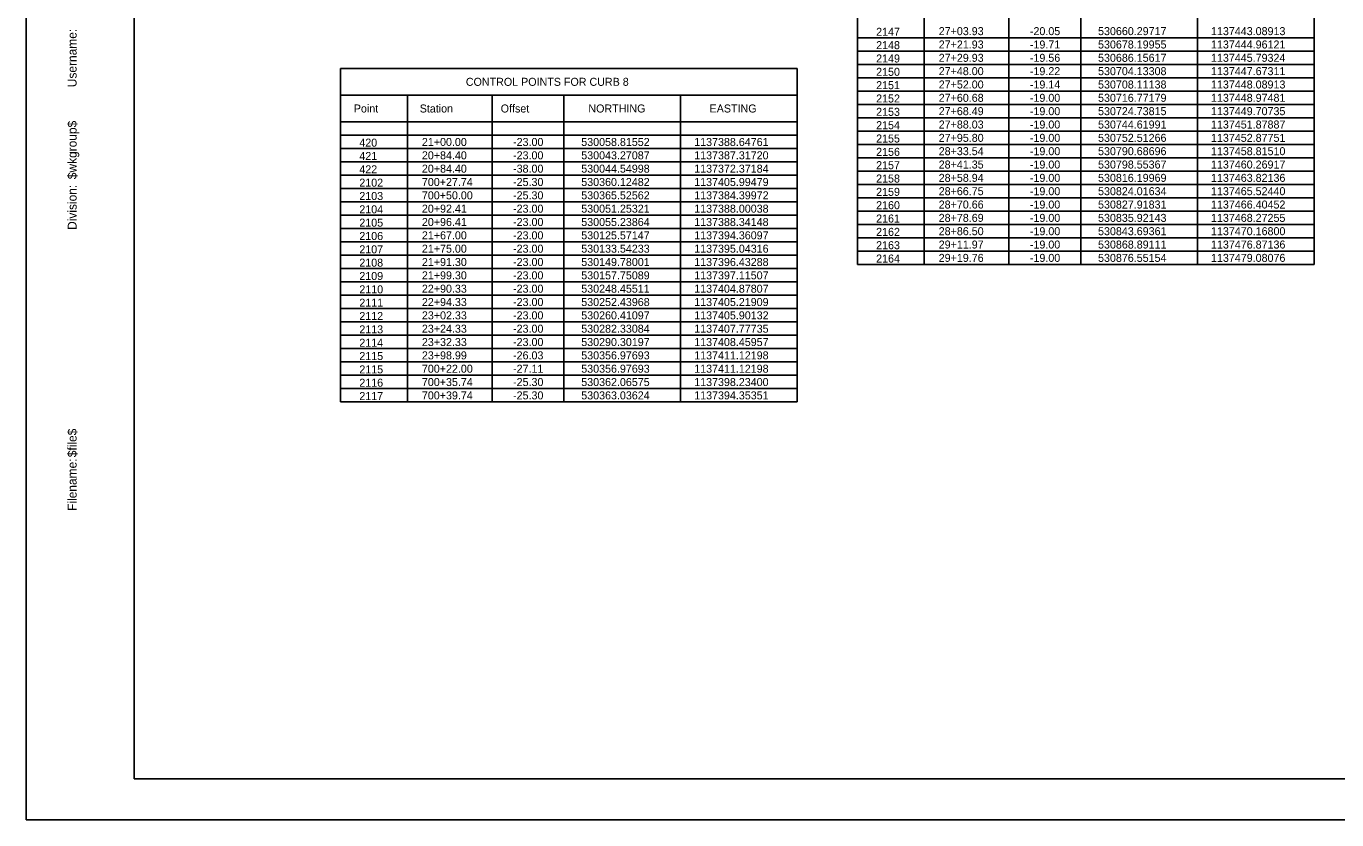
# Model space of a CAD drawing. Extents: x 0 to 850, y 0 to 550.
# Drawn here: x -0.1 to 491.2, y -0.1 to 297.4 of the extents above; entities that cross this region are included whole.
import ezdxf

# ---------------------------------------------------------------- set-up
doc = ezdxf.new("R2010")
doc.units = 0
for name, color, linetype in [('ANNOTATION', 7, 'Continuous'), ('BORDER', 7, 'Continuous'), ('Default', 7, 'Continuous'), ('H_V CONTROLS', 7, 'Continuous'), ('PLOT BOUNDARY', 7, 'Continuous')]:
    doc.layers.add(name, color=color, linetype=linetype)

msp = doc.modelspace()

# ---------------------------------------------------------------- linework, layer by layer
at = {"layer": 'BORDER'}
for p, q in [((40.33, 540.24), (40.33, 15.24)), ((40.33, 15.24), (840.33, 15.24))]:
    msp.add_line(p, q, dxfattribs=at)
at = {"layer": 'Default'}
msp.add_lwpolyline([(40.33, 15.24), (790.33, 15.24), (790.33, 540.26), (40.33, 540.26)], close=True, dxfattribs=at)
at = {"layer": 'H_V CONTROLS'}
for p, q in [((311.48, 483.15), (311.48, 208.15)), ((482.71, 483.15), (482.71, 208.15)), ((336.52, 473.15), (336.52, 208.15)), ((368.3, 473.15), (368.3, 208.15)), ((395.21, 473.15), (395.21, 208.15)), ((438.96, 473.15), (438.96, 208.15)), ((311.48, 293.15), (482.71, 293.15)), ((311.48, 288.15), (482.71, 288.15)), ((117.72, 281.6), (288.95, 281.6)), ((117.72, 281.6), (117.72, 156.6)), ((288.95, 281.6), (288.95, 156.6)), ((311.48, 283.15), (482.71, 283.15)), ((311.48, 278.15), (482.71, 278.15)), ((117.72, 271.6), (288.95, 271.6)), ((142.76, 271.6), (142.76, 156.6)), ((174.53, 271.6), (174.53, 156.6)), ((201.45, 271.6), (201.45, 156.6)), ((245.2, 271.6), (245.2, 156.6)), ((311.48, 273.15), (482.71, 273.15)), ((311.48, 268.15), (482.71, 268.15)), ((117.72, 261.6), (288.95, 261.6)), ((311.48, 263.15), (482.71, 263.15)), ((117.72, 256.6), (288.95, 256.6)), ((311.48, 258.15), (482.71, 258.15)), ((117.72, 251.6), (288.95, 251.6)), ((311.48, 253.15), (482.71, 253.15)), ((117.72, 246.6), (288.95, 246.6)), ((311.48, 248.15), (482.71, 248.15)), ((117.72, 241.6), (288.95, 241.6)), ((311.48, 243.15), (482.71, 243.15)), ((117.72, 236.6), (288.95, 236.6)), ((311.48, 238.15), (482.71, 238.15)), ((117.72, 231.6), (288.95, 231.6)), ((311.48, 233.15), (482.71, 233.15)), ((117.72, 226.6), (288.95, 226.6)), ((311.48, 228.15), (482.71, 228.15)), ((117.72, 221.6), (288.95, 221.6)), ((311.48, 223.15), (482.71, 223.15)), ((117.72, 216.6), (288.95, 216.6)), ((311.48, 218.15), (482.71, 218.15)), ((117.72, 211.6), (288.95, 211.6)), ((311.48, 213.15), (482.71, 213.15)), ((117.72, 206.6), (288.95, 206.6)), ((311.48, 208.15), (482.71, 208.15)), ((117.72, 201.6), (288.95, 201.6)), ((117.72, 196.6), (288.95, 196.6)), ((117.72, 191.6), (288.95, 191.6)), ((117.72, 186.6), (288.95, 186.6)), ((117.72, 181.6), (288.95, 181.6)), ((117.72, 176.6), (288.95, 176.6)), ((117.72, 171.6), (288.95, 171.6)), ((117.72, 166.6), (288.95, 166.6)), ((117.72, 161.6), (288.95, 161.6)), ((117.72, 156.6), (288.95, 156.6)), ((117.72, 156.6), (288.95, 156.6))]:
    msp.add_line(p, q, dxfattribs=at)
at = {"layer": 'PLOT BOUNDARY'}
msp.add_lwpolyline([(-0.13, -0.05), (849.87, -0.05), (849.87, 549.95), (-0.13, 549.95)], close=True, dxfattribs=at)

# ---------------------------------------------------------------- texts
at = {"layer": 'ANNOTATION'}
for s, p in [('2147', (318.51, 293.85)), ('27+03.93', (341.97, 294.1)), ('-20.05', (376.16, 294.1)), ('530660.29717', (401.71, 294.1)), ('1137443.08913', (444.06, 294.1)), ('2148', (318.51, 288.85)), ('27+21.93', (341.97, 289.1)), ('-19.71', (376.16, 289.1)), ('530678.19955', (401.71, 289.1)), ('1137444.96121', (444.06, 289.1)), ('2149', (318.51, 283.85)), ('27+29.93', (341.97, 284.1)), ('-19.56', (376.16, 284.1)), ('530686.15617', (401.71, 284.1)), ('1137445.79324', (444.06, 284.1)), ('2150', (318.51, 278.85)), ('27+48.00', (341.97, 279.1)), ('-19.22', (376.16, 279.1)), ('530704.13308', (401.71, 279.1)), ('1137447.67311', (444.06, 279.1)), ('2151', (318.51, 273.85)), ('27+52.00', (341.97, 274.1)), ('-19.14', (376.16, 274.1)), ('530708.11138', (401.71, 274.1)), ('1137448.08913', (444.06, 274.1)), ('2152', (318.51, 268.85)), ('27+60.68', (341.97, 269.1)), ('-19.00', (376.16, 269.1)), ('530716.77179', (401.71, 269.1)), ('1137448.97481', (444.06, 269.1)), ('2153', (318.51, 263.85)), ('27+68.49', (341.97, 264.1)), ('-19.00', (376.16, 264.1)), ('530724.73815', (401.71, 264.1)), ('1137449.70735', (444.06, 264.1)), ('2154', (318.51, 258.85)), ('27+88.03', (341.97, 259.1)), ('-19.00', (376.16, 259.1)), ('530744.61991', (401.71, 259.1)), ('1137451.87887', (444.06, 259.1)), ('21+00.00', (148.21, 252.55)), ('-23.00', (182.39, 252.55)), ('530058.81552', (207.95, 252.55)), ('1137388.64761', (250.3, 252.55)), ('2155', (318.51, 253.85)), ('27+95.80', (341.97, 254.1)), ('-19.00', (376.16, 254.1)), ('530752.51266', (401.71, 254.1)), ('1137452.87751', (444.06, 254.1)), ('420', (124.75, 252.3)), ('20+84.40', (148.21, 247.55)), ('-23.00', (182.39, 247.55)), ('530043.27087', (207.95, 247.55)), ('1137387.31720', (250.3, 247.55)), ('2156', (318.51, 248.85)), ('28+33.54', (341.97, 249.1)), ('-19.00', (376.16, 249.1)), ('530790.68696', (401.71, 249.1)), ('1137458.81510', (444.06, 249.1)), ('421', (124.75, 247.3)), ('2157', (318.51, 243.85)), ('28+41.35', (341.97, 244.1)), ('-19.00', (376.16, 244.1)), ('530798.55367', (401.71, 244.1)), ('1137460.26917', (444.06, 244.1)), ('422', (124.75, 242.3)), ('20+84.40', (148.21, 242.55)), ('-38.00', (182.39, 242.55)), ('530044.54998', (207.95, 242.55)), ('1137372.37184', (250.3, 242.55)), ('2158', (318.51, 238.85)), ('28+58.94', (341.97, 239.1)), ('-19.00', (376.16, 239.1)), ('530816.19969', (401.71, 239.1)), ('1137463.82136', (444.06, 239.1)), ('2102', (124.75, 237.3)), ('700+27.74', (148.21, 237.55)), ('-25.30', (182.39, 237.55)), ('530360.12482', (207.95, 237.55)), ('1137405.99479', (250.3, 237.55)), ('2159', (318.51, 233.85)), ('28+66.75', (341.97, 234.1)), ('-19.00', (376.16, 234.1)), ('530824.01634', (401.71, 234.1)), ('1137465.52440', (444.06, 234.1)), ('2103', (124.75, 232.3)), ('700+50.00', (148.21, 232.55)), ('-25.30', (182.39, 232.55)), ('530365.52562', (207.95, 232.55)), ('1137384.39972', (250.3, 232.55)), ('2160', (318.51, 228.85)), ('28+70.66', (341.97, 229.1)), ('-19.00', (376.16, 229.1)), ('530827.91831', (401.71, 229.1)), ('1137466.40452', (444.06, 229.1)), ('2104', (124.75, 227.3)), ('20+92.41', (148.21, 227.55)), ('-23.00', (182.39, 227.55)), ('530051.25321', (207.95, 227.55)), ('1137388.00038', (250.3, 227.55)), ('2161', (318.51, 223.85)), ('28+78.69', (341.97, 224.1)), ('-19.00', (376.16, 224.1)), ('530835.92143', (401.71, 224.1)), ('1137468.27255', (444.06, 224.1)), ('2105', (124.75, 222.3)), ('20+96.41', (148.21, 222.55)), ('-23.00', (182.39, 222.55)), ('530055.23864', (207.95, 222.55)), ('1137388.34148', (250.3, 222.55)), ('2162', (318.51, 218.85)), ('28+86.50', (341.97, 219.1)), ('-19.00', (376.16, 219.1)), ('530843.69361', (401.71, 219.1)), ('1137470.16800', (444.06, 219.1)), ('2106', (124.75, 217.3)), ('21+67.00', (148.21, 217.55)), ('-23.00', (182.39, 217.55)), ('530125.57147', (207.95, 217.55)), ('1137394.36097', (250.3, 217.55)), ('2163', (318.51, 213.85)), ('29+11.97', (341.97, 214.1)), ('-19.00', (376.16, 214.1)), ('530868.89111', (401.71, 214.1)), ('1137476.87136', (444.06, 214.1)), ('2107', (124.75, 212.3)), ('21+75.00', (148.21, 212.55)), ('-23.00', (182.39, 212.55)), ('530133.54233', (207.95, 212.55)), ('1137395.04316', (250.3, 212.55)), ('2164', (318.51, 208.85)), ('29+19.76', (341.97, 209.1)), ('-19.00', (376.16, 209.1)), ('530876.55154', (401.71, 209.1)), ('1137479.08076', (444.06, 209.1)), ('2108', (124.75, 207.3)), ('21+91.30', (148.21, 207.55)), ('-23.00', (182.39, 207.55)), ('530149.78001', (207.95, 207.55)), ('1137396.43288', (250.3, 207.55)), ('2109', (124.75, 202.3)), ('21+99.30', (148.21, 202.55)), ('-23.00', (182.39, 202.55)), ('530157.75089', (207.95, 202.55)), ('1137397.11507', (250.3, 202.55)), ('2110', (124.75, 197.3)), ('22+90.33', (148.21, 197.55)), ('-23.00', (182.39, 197.55)), ('530248.45511', (207.95, 197.55)), ('1137404.87807', (250.3, 197.55)), ('2111', (124.75, 192.3)), ('22+94.33', (148.21, 192.55)), ('-23.00', (182.39, 192.55)), ('530252.43968', (207.95, 192.55)), ('1137405.21909', (250.3, 192.55)), ('2112', (124.75, 187.3)), ('23+02.33', (148.21, 187.55)), ('-23.00', (182.39, 187.55)), ('530260.41097', (207.95, 187.55)), ('1137405.90132', (250.3, 187.55)), ('2113', (124.75, 182.3)), ('23+24.33', (148.21, 182.55)), ('-23.00', (182.39, 182.55)), ('530282.33084', (207.95, 182.55)), ('1137407.77735', (250.3, 182.55)), ('2114', (124.75, 177.3)), ('23+32.33', (148.21, 177.55)), ('-23.00', (182.39, 177.55)), ('530290.30197', (207.95, 177.55)), ('1137408.45957', (250.3, 177.55)), ('2115', (124.75, 172.3)), ('23+98.99', (148.21, 172.55)), ('-26.03', (182.39, 172.55)), ('530356.97693', (207.95, 172.55)), ('1137411.12198', (250.3, 172.55)), ('2115', (124.75, 167.3)), ('700+22.00', (148.21, 167.55)), ('-27.11', (182.39, 167.55)), ('530356.97693', (207.95, 167.55)), ('1137411.12198', (250.3, 167.55)), ('2116', (124.75, 162.3)), ('700+35.74', (148.21, 162.55)), ('-25.30', (182.39, 162.55)), ('530362.06575', (207.95, 162.55)), ('1137398.23400', (250.3, 162.55)), ('2117', (124.75, 157.3)), ('700+39.74', (148.21, 157.55)), ('-25.30', (182.39, 157.55)), ('530363.03624', (207.95, 157.55)), ('1137394.35351', (250.3, 157.55))]:
    msp.add_text(s, height=3, rotation=360, dxfattribs=at).set_placement(p)
at = {"layer": 'BORDER'}
for s, p in [('Username:', (18.76, 274.58)), ('$wkgroup$', (18.76, 240.09)), ('Division:', (18.76, 221.08)), ('$file$', (18.76, 135.87)), ('Filename:', (18.76, 115.74))]:
    msp.add_text(s, height=3.348, rotation=90, dxfattribs=at).set_placement(p)
at = {"layer": 'H_V CONTROLS'}
for s, p in [('CONTROL POINTS FOR CURB 8', (164.68, 275.1)), ('Point', (122.69, 265.1)), ('Station', (147.39, 265.1)), ('Offset', (177.76, 265.1)), ('NORTHING', (210.63, 265.1)), ('EASTING', (256.08, 265.1))]:
    msp.add_text(s, height=3, rotation=360, dxfattribs=at).set_placement(p)

doc.saveas('drawing.dxf')
